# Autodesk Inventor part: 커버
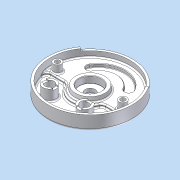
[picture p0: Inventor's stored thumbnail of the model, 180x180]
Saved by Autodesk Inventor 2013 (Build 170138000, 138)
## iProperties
Company: 한국ATC센터
Created: 2015-04
Part Number: 커버
Document SubType Name: Modeling
Designer: KYOUNG IL JANG
Density: 2.71 g/cm^3
Material: 알루미늄 6061
Mass: 1067.78 g
Surface Area: 1019.6 cm^2
Volume: 394.015 cm^3
Author: KYOUNG IL JANG
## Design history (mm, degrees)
sketch "스케치1"
  geometry: L1 (-59, -19)-(-59, 19); L2 (59, 19)-(59, -19); L3 (-41, 19)-(-41, -19); L4 (41, -19)-(41, 19); L5 (38.527, 33.023)-(55.442, 39.179); L6 (-38.527, 33.023)-(-55.442, 39.179); C1 r 90 at (0, 0); C2 r 95 at (0, 0); A1 r 59 centre (0, 19) between (59, 19) and (-59, 19); A2 r 59 centre (0, -19) between (-59, -19) and (59, -19); A3 r 41 centre (0, -19) between (-41, -19) and (41, -19); A4 r 41 centre (0, 19) between (41, 19) and (-41, 19); 2 further points
  constraints: 12 end point, 12 point on circle, 6 centre point, 4 tangent, 2 parallel, 2 point on line, 1 coincident, 1 horizontal alignment, 1 midpoint, 1 vertical, 1 vertical alignment, 3 other
  dimensions: "d2" = 180 diameter of C1; "d3" = 156 dimension on A2 A1; "d4" = 118 distance between parallel lines of L2 L1; "d5" = 18 distance between parallel lines of L2 L4; "d8" = 190 diameter of C2; "d120" = 140 deg angle of L6 L5; "d121" = 110 deg dimension on A1.centre point (0, 0) L5.end
extrude "돌출1" new body sketch "스케치1" distance "d6" = 14; taper "d7" = 0 deg
extrude "돌출2" join sketch "스케치1" distance "d9" = 13; taper "d10" = 0 deg
extrude "돌출3" cut sketch "스케치1" distance "d11" = 7; taper "d12" = 0 deg
sketch "스케치2"
  geometry: C1 r 11.5 at (0, 0); 1 further point
  constraints: 1 centre point, 1 coincident
  dimensions: "d13" = 23 diameter of C1
extrude "돌출4" cut sketch "스케치2" stored distance "d14" = 7; taper "d15" = 0 deg
fillet "모깎기1"
fillet "모깎기2"
sketch "스케치3"
  geometry: L1 (-73.724, 51.622)-(-77.819, 54.49); L2 (73.724, 51.622)-(77.819, 54.49); L3 (0, 0)-(0, -90); A1 r 95 centre (0, 0) between (-77.819, 54.49) and (77.819, 54.49) reference; A2 r 90 centre (0, 0) between (-73.724, 51.622) and (73.724, 51.622) reference; 1 further point
  constraints: 6 end point, 5 point on circle, 1 point on line, 1 vertical, 1 other
  dimensions: "d16" = 250 deg dimension on L2 L1
extrude "돌출5" join sketch "스케치3" distance "d17" = 5; taper "d18" = 0 deg
hole "구멍1" diameter "d21" = 50; stored, may be unused: countersink angle "d25" = 90 deg, drill point angle "d27" = 0 deg; dims "d19" = 10, "d20" = 10, "d22" = 6, "d23" = 4, "d24" = 2, "d26" = 5
fillet "모깎기3" dims "d28" = 0.3
fillet "모깎기5" dims "d30" = 3
sketch "스케치4"
  geometry: C1 r 35 at (0, 0); C2 r 25 at (0, 0); 1 further point
  constraints: 2 centre point, 1 coincident
  dimensions: "d32" = 70 diameter of C1 (derived); "d36" = 10 radial gap between concentric circles of C1 C2
extrude "돌출6" join sketch "스케치4" distance "d33" = 10; taper "d34" = 0 deg
feature "면 기울기2" dims angle "d37" = 10 deg
chamfer "모따기1" distance "d39" = 1; stored, may be unused: second distance "d40" = 2, angle "d41" = 45 deg
fillet "모깎기7" dims "d42" = 5
sketch "스케치5"
  geometry: L1 (-40.249, -12)-(-89.196, -12); L2 (40.249, -12)-(89.196, -12); A1 r 90 centre (0, 0) between (-89.196, -12) and (89.196, -12) reference; A2 r 42 centre (0, 0) between (-40.249, -12) and (40.249, -12); 1 further point
  constraints: 4 end point, 4 point on circle, 1 centre point, 1 collinear, 1 horizontal, 1 point on line
  dimensions: "d43" = 48 radial gap between concentric circles of A1 A2; "d44" = 12 distance from line of point (0, 0) L1
extrude "돌출7" cut sketch "스케치5" stored distance "d45" = 10; taper "d46" = 0 deg
fillet "모깎기8" dims "d47" = 10
chamfer "모따기2" distance "d49" = 1; stored, may be unused: second distance "d50" = 2, angle "d51" = 45 deg
sketch "스케치7"
  geometry: L1 (36.062, 36.062)-(50.912, 50.912); L2 (-36.062, 36.062)-(-50.912, 50.912); A1 r 72 centre (0, 0) between (50.912, 50.912) and (-50.912, 50.912); A2 r 51 centre (0, 0) between (36.062, 36.062) and (-36.062, 36.062); 1 further point
  constraints: 8 point on circle, 4 end point, 2 centre point, 2 point on line, 1 coincident, 1 horizontal alignment
  dimensions: "d54" = 72 radius of A1; "d55" = 21 radial gap between concentric circles of A1 A2; "d56" = 90 deg angle of L2 L1
extrude "돌출8" join sketch "스케치7" distance "d57" = 5; taper "d58" = 0 deg
fillet "모깎기10" dims "d59" = 5
fillet "모깎기11" dims "d60" = 5
fillet "모깎기12" dims "d61" = 3
sketch "스케치6"
  geometry: C1 r 68 at (0, 0); 1 further point
  constraints: 1 centre point, 1 other
  dimensions: "d119" = 136 diameter of C1
feature "엠보싱1" sketch "스케치6" dims "d62" = 0.5, "d63" = 0
sketch "스케치8"
  geometry: C1 r 9 at (74, 0); C2 r 9 at (-74, 0); A1 r 74 centre (0, 0) between (74, 0) and (-74, 0); 1 further point
  constraints: 3 centre point, 2 horizontal alignment, 2 point on circle, 1 coincident, 1 equal radius
  dimensions: "d64" = 18 diameter of C1; "d65" = 148 diameter of A1
extrude "돌출9" join sketch "스케치8" stored distance "d66" = 5; taper "d67" = 0 deg
sketch "스케치11"
  geometry: C1 r 15 at (40, -52); C2 r 15 at (-40, -52); 1 further point
  constraints: 2 centre point, 1 equal radius, 1 horizontal alignment
  dimensions: "d83" = 52 vertical distance of point (0, 0) C1.centre; "d84" = 80 distance of C2.centre C1.centre; "d85" = 40 horizontal distance of point (0, 0) C1.centre (= 0.5 x d84); "d86" = 30 diameter of C1
extrude "돌출10" join sketch "스케치11" stored distance "d87" = 5; taper "d88" = 0 deg
node "구멍3"
node "구멍5"
hole "구멍6" diameter "d93" = 20; stored, may be unused: countersink angle "d97" = 90 deg, drill point angle "d99" = 118 deg; dims "d91" = 10, "d92" = 10, "d94" = 6, "d95" = 4, "d96" = 2, "d98" = 8
hole "구멍7" diameter "d102" = 20; stored, may be unused: countersink angle "d106" = 90 deg, drill point angle "d108" = 118 deg; dims "d100" = 10, "d101" = 10, "d103" = 6, "d104" = 4, "d105" = 2, "d107" = 8
sketch "스케치13"
  geometry: L1 (6, -13.748)-(6, -8); L2 (6, 8)-(6, 13.748); L3 (-6, -13.748)-(-6, -8); L4 (-6, 8)-(-6, 13.748); L5 (-66.252, -6)-(-72, -6); L6 (-88, -6)-(-93.748, -6); L7 (-66.252, 6)-(-72, 6); L8 (-88, 6)-(-93.748, 6); A1 r 15 centre (0, 0) between (6, -13.748) and (6, 13.748) reference; A2 r 10 centre (0, 0) between (6, -8) and (6, 8) reference; A3 r 15 centre (-80, 0) between (-66.252, -6) and (-93.748, -6) reference; A4 r 10 centre (-80, 0) between (-72, -6) and (-88, -6) reference; 1 further point
  constraints: 16 end point, 16 point on circle, 4 equal length, 3 collinear, 2 point on line, 1 perpendicular, 1 vertical
  dimensions: "d109" = 12 distance between parallel lines of L3 L1; "d110" = 6 distance from line of A1.centre L1 (= 0.5 x d109); "d111" = 12 distance between parallel lines of L7 L5; "d112" = 6 distance from line of A3.centre L5 (= 0.5 x d111)
extrude "돌출12" cut sketch "스케치13" distance "d113" = 3; taper "d114" = 0 deg
fillet "모깎기13" dims "d115" = 3
fillet "모깎기14" dims "d116" = 1
node "솔리드1"
sketch "스케치9"
  geometry: 1 further point
hole "구멍2" sketch "스케치9" diameter "d68" = 11; stored, may be unused: countersink angle "d72" = 90 deg, drill point angle "d74" = 0 deg; dims "d69" = 6, "d70" = 18, "d71" = 11, "d73" = 8
sketch "스케치10"
  geometry: 1 further point
hole "구멍4" sketch "스케치10" diameter "d75" = 11; stored, may be unused: countersink angle "d79" = 90 deg, drill point angle "d81" = 0 deg; dims "d76" = 6, "d77" = 18, "d78" = 11, "d80" = 8
